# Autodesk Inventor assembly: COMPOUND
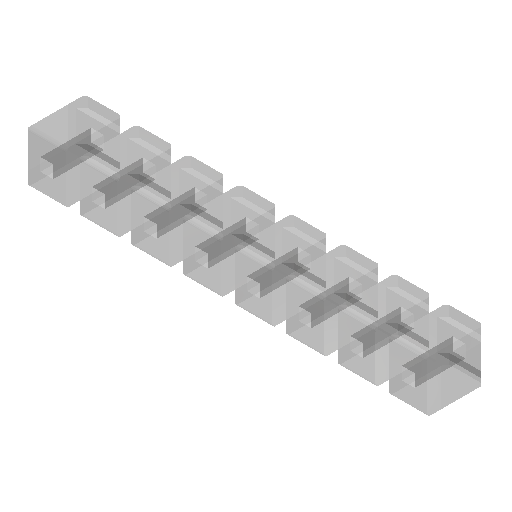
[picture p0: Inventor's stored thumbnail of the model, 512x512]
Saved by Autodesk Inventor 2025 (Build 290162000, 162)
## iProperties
Created: 2025-05
Part Number: COMPOUND
Document SubType Name: Assembly
Designer: R5800u
Author: R5800u
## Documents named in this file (9)
- C:\Users\R5800u\Desktop\drone\c3\ESP32-C3 Super Mini breakout expansion board module -Assembly\COMPOUND_5.iam
- C:\Users\R5800u\Desktop\drone\c3\ESP32-C3 Super Mini breakout expansion board module -Assembly\COMPOUND_40.ipt
- C:\Users\R5800u\Desktop\drone\c3\ESP32-C3 Super Mini breakout expansion board module -Assembly\COMPOUND_41.ipt
- C:\Users\R5800u\Desktop\drone\c3\ESP32-C3 Super Mini breakout expansion board module -Assembly\COMPOUND_42.ipt
- C:\Users\R5800u\Desktop\drone\c3\ESP32-C3 Super Mini breakout expansion board module -Assembly\COMPOUND_43.ipt
- C:\Users\R5800u\Desktop\drone\c3\ESP32-C3 Super Mini breakout expansion board module -Assembly\COMPOUND_44.ipt
- C:\Users\R5800u\Desktop\drone\c3\ESP32-C3 Super Mini breakout expansion board module -Assembly\COMPOUND_45.ipt
- C:\Users\R5800u\Desktop\drone\c3\ESP32-C3 Super Mini breakout expansion board module -Assembly\COMPOUND_46.ipt
- C:\Users\R5800u\Desktop\drone\c3\ESP32-C3 Super Mini breakout expansion board module -Assembly\COMPOUND_47.ipt
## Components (8 placed, 8 different names)
1. 49
2. 50
3. 51
4. 52
5. 53
6. 54
7. 55
8. 56
